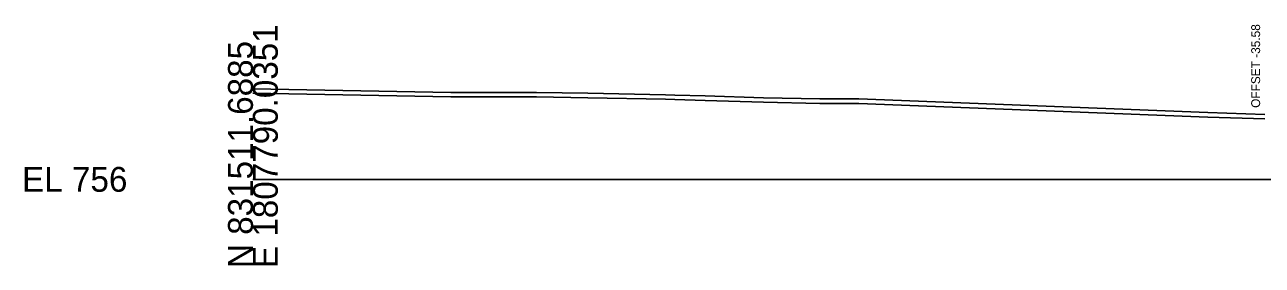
# Model space of a CAD drawing. Extents: x -26 to 303, y -29 to 2535.
# Drawn here: x -25.7 to 113.7, y -9.7 to 17.4 of the extents above; entities that cross this region are included whole.
import ezdxf

# ---------------------------------------------------------------- set-up
doc = ezdxf.new("R2010")
doc.units = 0
for name, color, linetype in [('DESIGN - PROFILE - Private Drive Vertical Curve Text', 7, 'Continuous'), ('DESIGN - SHEET - Light Grid', 7, 'Continuous'), ('SURVEY - AERIAL SURVEY - Mapping Setup - MAPPING LIMITS', 7, 'Continuous'), ('SURVEY - AERIAL SURVEY - Obscured Area', 7, 'Continuous')]:
    doc.layers.add(name, color=color, linetype=linetype)

msp = doc.modelspace()

# ---------------------------------------------------------------- linework, layer by layer
at = {"layer": 'DESIGN - SHEET - Light Grid'}
msp.add_line((0, 0), (150, 0), dxfattribs=at)
at = {"layer": 'SURVEY - AERIAL SURVEY - Mapping Setup - MAPPING LIMITS'}
msp.add_lwpolyline([(0, 10.21), (22.27, 9.8), (31.95, 9.8), (37.72, 9.71), (46.48, 9.53), (47.53, 9.49), (50.92, 9.41), (57.48, 9.2), (63.85, 9.07), (68.24, 9.07), (107.54, 7.52), (113.95, 7.33)], dxfattribs=at)
at = {"layer": 'SURVEY - AERIAL SURVEY - Obscured Area'}
for p, q in [((0, 9.71), (22.27, 9.3)), ((22.27, 9.3), (31.95, 9.3)), ((31.95, 9.3), (37.72, 9.21)), ((37.72, 9.21), (46.48, 9.03)), ((46.48, 9.03), (47.53, 8.99)), ((47.53, 8.99), (50.92, 8.91)), ((50.92, 8.91), (57.48, 8.7)), ((57.48, 8.7), (63.85, 8.57)), ((63.85, 8.57), (68.24, 8.57)), ((68.24, 8.57), (107.54, 7.02)), ((107.54, 7.02), (113.95, 6.83))]:
    msp.add_line(p, q, dxfattribs=at)

# ---------------------------------------------------------------- texts
at = {"layer": 'DESIGN - PROFILE - Private Drive Vertical Curve Text'}
msp.add_text('OFFSET -35.58', height=1, rotation=90, dxfattribs=at).set_placement((113.42, 8.06))
at = {"layer": 'DESIGN - SHEET - Light Grid'}
for s, p in [('E 1807790.0351', (2.8, -10)), ('N 831511.6885', (0, -10))]:
    msp.add_text(s, height=2.8, rotation=90, dxfattribs=at).set_placement(p)
msp.add_text('EL 756', height=2.8, dxfattribs=at).set_placement((-26, -1.4))

doc.saveas('drawing.dxf')
